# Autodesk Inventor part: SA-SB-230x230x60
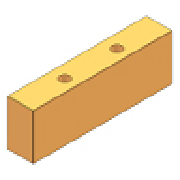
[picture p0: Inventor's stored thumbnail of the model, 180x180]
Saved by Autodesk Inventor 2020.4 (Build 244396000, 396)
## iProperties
Created: 2019-01
Part Number: SA-SB-230x230x60
Material: S 55 C
Description: Spacer Block
Document SubType Name: Modeling
Designer: mel
Standard Revision: 1
Manufacturer: FUTABA
Language: fr-FR
Size Designation: 230x230x60
Categories: <MemberInstance><Categories><Category DisplayName="Moule" InternalName="349578f2-f4d4-4954-8c09-8e99297a61c0" Mnemonic="MOLD"><Category DisplayName="Plaque de m
Density: 7.85 g/cm^3
Appearance: Orange (Pale)
IsCustomPart: 1
Author: mel
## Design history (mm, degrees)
sketch "Sketch1"
  geometry: L1 (-72, 115)-(-115, 115); L2 (-115, 115)-(-115, -115); L3 (-115, -115)-(-72, -115); L4 (-72, -115)-(-72, 115); L5 (115, 115)-(115, -115); L6 (72, -115)-(72, 115); L7 (72, 115)-(115, 115); L8 (72, -115)-(115, -115); 5 further points
  constraints: 16 end point, 3 parallel, 2 horizontal alignment, 2 midpoint, 2 perpendicular, 1 horizontal, 1 vertical
  dimensions: "d85" = 230 distance between parallel lines of L3 L1 (= L); "d86" = 43 distance between parallel lines of L4 L2 (= W_); "d88" = 43 distance between parallel lines of L5 L6 (= W_); "d89" = 115 distance from line of point (0, 0) L2 (= 0.5 x M_W); "d93" = 230 distance between parallel lines of L8 L7 (= L); "d94" = 115 distance from line of point (0, 0) L5 (= 0.5 x M_W); "d98" = 53 vertical distance of point (-92.5, 53) point (0, 0) (= 0.5 x S1_L); "d100" = 92.5 horizontal distance of point (-92.5, 53) point (0, 0) (= 0.5 x S1_W); "d101" = 92.5 horizontal distance of point (92.5, 53) point (0, 0) (= 0.5 x S1_W); "d102" = 53 vertical distance of point (0, 0) point (92.5, 53) (= 0.5 x S1_L)
extrude "Extrusion1" new body sketch "Sketch1" distance "d20" = 60 (= H_); taper "d30" = 0 deg
extrude "Extrusion2" join sketch "Sketch1" distance "d95" = 60 (= H_); taper "d96" = 0 deg
hole "Hole1" sketch "Sketch1" diameter "d129" = 14 (= S1_d1); stored, may be unused: countersink angle "d133" = 90 deg, drill point angle "d135" = 0 deg; dims "d130" = 6, "d131" = 4, "d132" = 2, "d134" = 60 (= H_)
pattern_linear "Rectangular Pattern1" dims "d156" = 106 (computed from S1_L, Ns)
hole "Hole2" sketch "Sketch1" diameter "d122" = 14 (= S1_d1); stored, may be unused: countersink angle "d126" = 90 deg, drill point angle "d128" = 0 deg; dims "d123" = 6, "d124" = 4, "d125" = 2, "d127" = 60 (= H_)
pattern_linear "Rectangular Pattern2" dims "d153" = 106 (computed from S1_L, Ns)
workplane "Work Plane1"
workplane "Work Plane2"
chamfer "Chamfer1" distance "d157" = 0.5; stored, may be unused: second distance "d158" = 2, angle "d159" = 45 deg
chamfer "Chamfer2" distance "d160" = 0.5; stored, may be unused: second distance "d161" = 2, angle "d162" = 45 deg
body "Solid1"
other parameters: "L" = 230 [user parameter; used in 2 equation terms], "W_" = 43 [user parameter; used in 2 equation terms], "H_" = 60 [user parameter; used in 5 equation terms], "S1_L" = 106 [user parameter; used in 4 equation terms], "S1_W" = 185 [user parameter; used in 2 equation terms], "S1_d1" = 14 [user parameter; used in 2 equation terms], "d164" = 0
